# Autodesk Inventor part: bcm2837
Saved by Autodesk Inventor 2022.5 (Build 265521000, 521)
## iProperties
Created: 2024-12
Part Number: bcm2837
Material: Generic
Document SubType Name: Modeling
Designer: AdminForWorker
Density: 1 g/cm^3
Appearance: Default
Title: bcm2837 v1
Author: AdminForWorker
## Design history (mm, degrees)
feature "Body1"
feature "Body64"
feature "Body112"
feature "Body113"
feature "Body114"
feature "Body115"
feature "Body65"
feature "Body66"
feature "Body67"
feature "Body68"
feature "Body69"
feature "Body70"
feature "Body71"
feature "Body72"
feature "Body73"
feature "Body74"
feature "Body75"
feature "Body116"
feature "Body117"
feature "Body118"
feature "Body119"
feature "Body106"
feature "Body120"
feature "Body121"
feature "Body122"
feature "Body123"
feature "Body109"
feature "Body103"
feature "Body100"
feature "Body97"
feature "Body94"
feature "Body91"
feature "Body88"
feature "Body85"
feature "Body82"
feature "Body79"
feature "Body76"
feature "Body124"
feature "Body125"
feature "Body126"
feature "Body127"
feature "Body107"
feature "Body128"
feature "Body129"
feature "Body130"
feature "Body131"
feature "Body110"
feature "Body104"
feature "Body101"
feature "Body98"
feature "Body95"
feature "Body92"
feature "Body89"
feature "Body86"
feature "Body83"
feature "Body80"
feature "Body77"
feature "Body132"
feature "Body133"
feature "Body134"
feature "Body135"
feature "Body108"
feature "Body136"
feature "Body137"
feature "Body138"
feature "Body139"
feature "Body111"
feature "Body105"
feature "Body102"
feature "Body99"
feature "Body96"
feature "Body93"
feature "Body90"
feature "Body87"
feature "Body84"
feature "Body81"
feature "Body78"
feature "Body140"
feature "Body141"
feature "Body142"
feature "Body143"
feature "Body144"
feature "Body145"
body "Solid1"
body "Solid2"
body "Solid3"
body "Solid4"
body "Solid5"
body "Solid6"
body "Solid7"
body "Solid8"
body "Solid9"
body "Solid10"
body "Solid11"
body "Solid12"
body "Solid13"
body "Solid14"
body "Solid15"
body "Solid16"
body "Solid17"
body "Solid18"
body "Solid19"
body "Solid20"
body "Solid21"
body "Solid22"
body "Solid23"
body "Solid24"
body "Solid25"
body "Solid26"
body "Solid27"
body "Solid28"
body "Solid29"
body "Solid30"
body "Solid31"
body "Solid32"
body "Solid33"
body "Solid34"
body "Solid35"
body "Solid36"
body "Solid37"
body "Solid38"
body "Solid39"
body "Solid40"
body "Solid41"
body "Solid42"
body "Solid43"
body "Solid44"
body "Solid45"
body "Solid46"
body "Solid47"
body "Solid48"
body "Solid49"
body "Solid50"
body "Solid51"
body "Solid52"
body "Solid53"
body "Solid54"
body "Solid55"
body "Solid56"
body "Solid57"
body "Solid58"
body "Solid59"
body "Solid60"
body "Solid61"
body "Solid62"
body "Solid63"
body "Solid64"
body "Solid65"
body "Solid66"
body "Solid67"
body "Solid68"
body "Solid69"
body "Solid70"
body "Solid71"
body "Solid72"
body "Solid73"
body "Solid74"
body "Solid75"
body "Solid76"
body "Solid77"
body "Solid78"
body "Solid79"
body "Solid80"
body "Solid81"
body "Solid82"
body "Solid83"
